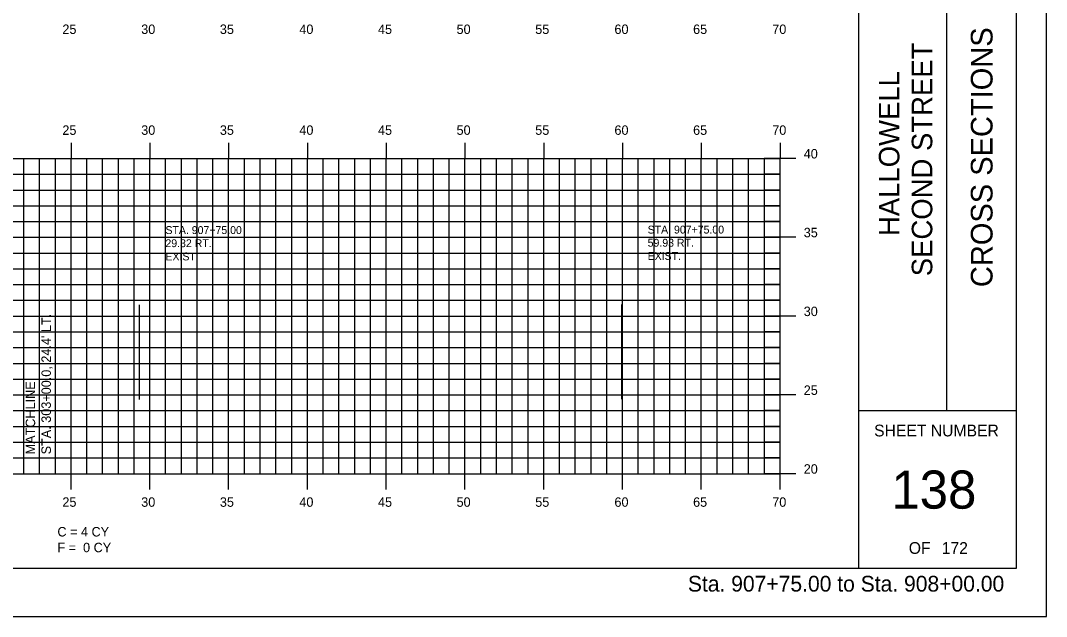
# Model space of a CAD drawing. Extents: x 1026131 to 1026301, y 394697 to 394807.
# Drawn here: x 1026236.1 to 1026301.3, y 394696.5 to 394734.4 of the extents above; entities that cross this region are included whole.
import ezdxf

# ---------------------------------------------------------------- set-up
doc = ezdxf.new("R2010")
doc.units = 0
for name, color, linetype in [('ANNOTATION', 7, 'Continuous'), ('BORDER', 7, 'Continuous'), ('D_Text_Monospaced', 7, 'Continuous'), ('H_V ANNOTATION', 7, 'Continuous'), ('HIGHWAY_TITLE', 7, 'Continuous'), ('MAJOR', 7, 'Continuous'), ('MINOR', 7, 'Continuous'), ('PLOT BOUNDARY', 7, 'Continuous'), ('S_Utilities_UG_Sanitary_Sewer', 7, 'Continuous')]:
    doc.layers.add(name, color=color, linetype=linetype)

msp = doc.modelspace()

# ---------------------------------------------------------------- linework, layer by layer
at = {"layer": 'BORDER'}
for p, q in [((1026289.345, 394699.607), (1026289.345, 394804.61)), ((1026299.345, 394699.607), (1026299.345, 394804.607)), ((1026294.936, 394709.61), (1026294.936, 394744.61)), ((1026289.345, 394709.61), (1026299.345, 394709.61)), ((1026139.345, 394699.607), (1026299.345, 394699.607))]:
    msp.add_line(p, q, dxfattribs=at)
at = {"layer": 'MAJOR'}
for p, q in [((1026239.344, 394726.609), (1026239.344, 394725.607)), ((1026244.344, 394726.609), (1026244.344, 394725.607)), ((1026249.344, 394726.609), (1026249.344, 394725.607)), ((1026254.344, 394726.609), (1026254.344, 394725.607)), ((1026259.344, 394726.609), (1026259.344, 394725.607)), ((1026264.344, 394726.609), (1026264.344, 394725.607)), ((1026269.344, 394726.609), (1026269.344, 394725.607)), ((1026274.344, 394726.609), (1026274.344, 394725.607)), ((1026279.344, 394726.609), (1026279.344, 394725.607)), ((1026284.344, 394726.609), (1026284.344, 394725.607)), ((1026144.344, 394725.607), (1026284.344, 394725.607)), ((1026239.344, 394705.607), (1026239.344, 394725.607)), ((1026244.344, 394705.607), (1026244.344, 394725.607)), ((1026249.344, 394705.607), (1026249.344, 394725.607)), ((1026254.344, 394705.607), (1026254.344, 394725.607)), ((1026259.344, 394705.607), (1026259.344, 394725.607)), ((1026264.344, 394705.607), (1026264.344, 394725.607)), ((1026269.344, 394705.607), (1026269.344, 394725.607)), ((1026274.344, 394705.607), (1026274.344, 394725.607)), ((1026279.344, 394705.607), (1026279.344, 394725.607)), ((1026285.346, 394725.607), (1026283.342, 394725.607)), ((1026284.344, 394705.607), (1026284.344, 394725.607)), ((1026144.344, 394720.607), (1026284.344, 394720.607)), ((1026285.346, 394720.607), (1026283.342, 394720.607)), ((1026144.344, 394715.607), (1026284.344, 394715.607)), ((1026285.346, 394715.607), (1026283.342, 394715.607)), ((1026144.344, 394710.607), (1026284.344, 394710.607)), ((1026285.346, 394710.607), (1026283.342, 394710.607)), ((1026144.344, 394705.607), (1026284.344, 394705.607)), ((1026239.344, 394704.605), (1026239.344, 394705.607)), ((1026244.344, 394704.605), (1026244.344, 394705.607)), ((1026249.344, 394704.605), (1026249.344, 394705.607)), ((1026254.344, 394704.605), (1026254.344, 394705.607)), ((1026259.344, 394704.605), (1026259.344, 394705.607)), ((1026264.344, 394704.605), (1026264.344, 394705.607)), ((1026269.344, 394704.605), (1026269.344, 394705.607)), ((1026274.344, 394704.605), (1026274.344, 394705.607)), ((1026279.344, 394704.605), (1026279.344, 394705.607)), ((1026285.346, 394705.607), (1026283.342, 394705.607)), ((1026284.344, 394704.605), (1026284.344, 394705.607))]:
    msp.add_line(p, q, dxfattribs=at)
at = {"layer": 'MINOR'}
for p, q in [((1026236.344, 394705.607), (1026236.344, 394725.607)), ((1026237.344, 394705.607), (1026237.344, 394725.607)), ((1026238.344, 394705.607), (1026238.344, 394725.607)), ((1026240.344, 394705.607), (1026240.344, 394725.607)), ((1026241.344, 394705.607), (1026241.344, 394725.607)), ((1026242.344, 394705.607), (1026242.344, 394725.607)), ((1026243.344, 394705.607), (1026243.344, 394725.607)), ((1026245.344, 394705.607), (1026245.344, 394725.607)), ((1026246.344, 394705.607), (1026246.344, 394725.607)), ((1026247.344, 394705.607), (1026247.344, 394725.607)), ((1026248.344, 394705.607), (1026248.344, 394725.607)), ((1026250.344, 394705.607), (1026250.344, 394725.607)), ((1026251.344, 394705.607), (1026251.344, 394725.607)), ((1026252.344, 394705.607), (1026252.344, 394725.607)), ((1026253.344, 394705.607), (1026253.344, 394725.607)), ((1026255.344, 394705.607), (1026255.344, 394725.607)), ((1026256.344, 394705.607), (1026256.344, 394725.607)), ((1026257.344, 394705.607), (1026257.344, 394725.607)), ((1026258.344, 394705.607), (1026258.344, 394725.607)), ((1026260.344, 394705.607), (1026260.344, 394725.607)), ((1026261.344, 394705.607), (1026261.344, 394725.607)), ((1026262.344, 394705.607), (1026262.344, 394725.607)), ((1026263.344, 394705.607), (1026263.344, 394725.607)), ((1026265.344, 394705.607), (1026265.344, 394725.607)), ((1026266.344, 394705.607), (1026266.344, 394725.607)), ((1026267.344, 394705.607), (1026267.344, 394725.607)), ((1026268.344, 394705.607), (1026268.344, 394725.607)), ((1026270.344, 394705.607), (1026270.344, 394725.607)), ((1026271.344, 394705.607), (1026271.344, 394725.607)), ((1026272.344, 394705.607), (1026272.344, 394725.607)), ((1026273.344, 394705.607), (1026273.344, 394725.607)), ((1026275.344, 394705.607), (1026275.344, 394725.607)), ((1026276.344, 394705.607), (1026276.344, 394725.607)), ((1026277.344, 394705.607), (1026277.344, 394725.607)), ((1026278.344, 394705.607), (1026278.344, 394725.607)), ((1026280.344, 394705.607), (1026280.344, 394725.607)), ((1026281.344, 394705.607), (1026281.344, 394725.607)), ((1026282.344, 394705.607), (1026282.344, 394725.607)), ((1026283.344, 394705.607), (1026283.344, 394725.607)), ((1026144.344, 394724.607), (1026284.344, 394724.607)), ((1026284.344, 394724.607), (1026283.342, 394724.607)), ((1026144.344, 394723.607), (1026284.344, 394723.607)), ((1026284.344, 394723.607), (1026283.342, 394723.607)), ((1026144.344, 394722.607), (1026284.344, 394722.607)), ((1026284.344, 394722.607), (1026283.342, 394722.607)), ((1026144.344, 394721.607), (1026284.344, 394721.607)), ((1026284.344, 394721.607), (1026283.342, 394721.607)), ((1026144.344, 394719.607), (1026284.344, 394719.607)), ((1026284.344, 394719.607), (1026283.342, 394719.607)), ((1026144.344, 394718.607), (1026284.344, 394718.607)), ((1026284.344, 394718.607), (1026283.342, 394718.607)), ((1026144.344, 394717.607), (1026284.344, 394717.607)), ((1026284.344, 394717.607), (1026283.342, 394717.607)), ((1026144.344, 394716.607), (1026284.344, 394716.607)), ((1026284.344, 394716.607), (1026283.342, 394716.607)), ((1026144.344, 394714.607), (1026284.344, 394714.607)), ((1026284.344, 394714.607), (1026283.342, 394714.607)), ((1026144.344, 394713.607), (1026284.344, 394713.607)), ((1026284.344, 394713.607), (1026283.342, 394713.607)), ((1026144.344, 394712.607), (1026284.344, 394712.607)), ((1026284.344, 394712.607), (1026283.342, 394712.607)), ((1026144.344, 394711.607), (1026284.344, 394711.607)), ((1026284.344, 394711.607), (1026283.342, 394711.607)), ((1026144.344, 394709.607), (1026284.344, 394709.607)), ((1026284.344, 394709.607), (1026283.342, 394709.607)), ((1026144.344, 394708.607), (1026284.344, 394708.607)), ((1026284.344, 394708.607), (1026283.342, 394708.607)), ((1026144.344, 394707.607), (1026284.344, 394707.607)), ((1026284.344, 394707.607), (1026283.342, 394707.607)), ((1026144.344, 394706.607), (1026284.344, 394706.607)), ((1026284.344, 394706.607), (1026283.342, 394706.607))]:
    msp.add_line(p, q, dxfattribs=at)
at = {"layer": 'PLOT BOUNDARY'}
msp.add_lwpolyline([(1026131.251, 394696.548), (1026301.251, 394696.548), (1026301.251, 394806.548), (1026131.251, 394806.548)], close=True, dxfattribs=at)
at = {"layer": 'S_Utilities_UG_Sanitary_Sewer'}
for p, q in [((1026243.663, 394716.316), (1026243.663, 394710.316)), ((1026274.27, 394716.346), (1026274.27, 394710.346))]:
    msp.add_line(p, q, dxfattribs=at)

# ---------------------------------------------------------------- texts
at = {"layer": 'ANNOTATION'}
for s, p in [("STA. 303+00.0, 24.4' LT.", (1026238.062, 394706.832)), ('MATCHLINE', (1026237.062, 394706.832))]:
    msp.add_text(s, height=0.6, rotation=90, dxfattribs=at).set_placement(p)
for s, p in [('C = 4 CY', (1026238.476, 394701.623)), ('F =  0 CY', (1026238.476, 394700.623))]:
    msp.add_text(s, height=0.6, dxfattribs=at).set_placement(p)
at = {"layer": 'BORDER'}
for s, height, rotation, p in [('CROSS SECTIONS', 1.37787, 90, (1026297.829, 394717.444)), ('SHEET NUMBER', 0.74527, 360, (1026290.31, 394707.973)), ('138', 2.4194, 360, (1026291.405, 394703.389)), ('OF', 0.7453, 360, (1026292.511, 394700.52)), ('172', 0.7453, 360, (1026294.601, 394700.52))]:
    msp.add_text(s, height=height, rotation=rotation, dxfattribs=at).set_placement(p)
at = {"layer": 'D_Text_Monospaced'}
for s, height, p in [('STA. 907+75.00', 0.49998, (1026245.33, 394720.814)), ('STA. 907+75.00', 0.49998, (1026275.937, 394720.844)), ('29.32 RT.', 0.5, (1026245.33, 394719.98)), ('59.93 RT.', 0.5, (1026275.937, 394720.01)), ('EXIST. ', 0.5, (1026245.33, 394719.14)), ('EXIST. ', 0.5, (1026275.937, 394719.17))]:
    msp.add_text(s, height=height, dxfattribs=at).set_placement(p)
at = {"layer": 'H_V ANNOTATION'}
for s, height, p in [('25', 0.6, (1026238.79, 394733.507)), ('30', 0.6, (1026243.793, 394733.507)), ('35', 0.6, (1026248.785, 394733.507)), ('40', 0.6, (1026253.83, 394733.507)), ('45', 0.6, (1026258.822, 394733.507)), ('50', 0.6, (1026263.809, 394733.507)), ('55', 0.6, (1026268.801, 394733.507)), ('60', 0.6, (1026273.83, 394733.507)), ('65', 0.6, (1026278.822, 394733.507)), ('70', 0.6, (1026283.846, 394733.507)), ('25', 0.6, (1026238.79, 394727.107)), ('30', 0.6, (1026243.793, 394727.107)), ('35', 0.6, (1026248.785, 394727.107)), ('40', 0.6, (1026253.83, 394727.107)), ('45', 0.6, (1026258.822, 394727.107)), ('50', 0.6, (1026263.809, 394727.107)), ('55', 0.6, (1026268.801, 394727.107)), ('60', 0.6, (1026273.83, 394727.107)), ('65', 0.6, (1026278.822, 394727.107)), ('70', 0.6, (1026283.846, 394727.107)), ('40', 0.6, (1026285.844, 394725.607)), ('35', 0.6, (1026285.844, 394720.607)), ('30', 0.6, (1026285.844, 394715.607)), ('25', 0.6, (1026285.844, 394710.607)), ('20', 0.6, (1026285.844, 394705.607)), ('25', 0.6, (1026238.79, 394703.507)), ('30', 0.6, (1026243.793, 394703.507)), ('35', 0.6, (1026248.785, 394703.507)), ('40', 0.6, (1026253.83, 394703.507)), ('45', 0.6, (1026258.822, 394703.507)), ('50', 0.6, (1026263.809, 394703.507)), ('55', 0.6, (1026268.801, 394703.507)), ('60', 0.6, (1026273.83, 394703.507)), ('65', 0.6, (1026278.822, 394703.507)), ('70', 0.6, (1026283.846, 394703.507)), ('Sta. 907+75.00 to Sta. 908+00.00', 1.0002, (1026278.49, 394698.126))]:
    msp.add_text(s, height=height, dxfattribs=at).set_placement(p)
at = {"layer": 'HIGHWAY_TITLE'}
for s, height, p in [('SECOND STREET', 1.30428, (1026294.004, 394718.134)), ('HALLOWELL', 1.3043, (1026291.917, 394720.684))]:
    msp.add_text(s, height=height, rotation=90, dxfattribs=at).set_placement(p)

doc.saveas('drawing.dxf')
